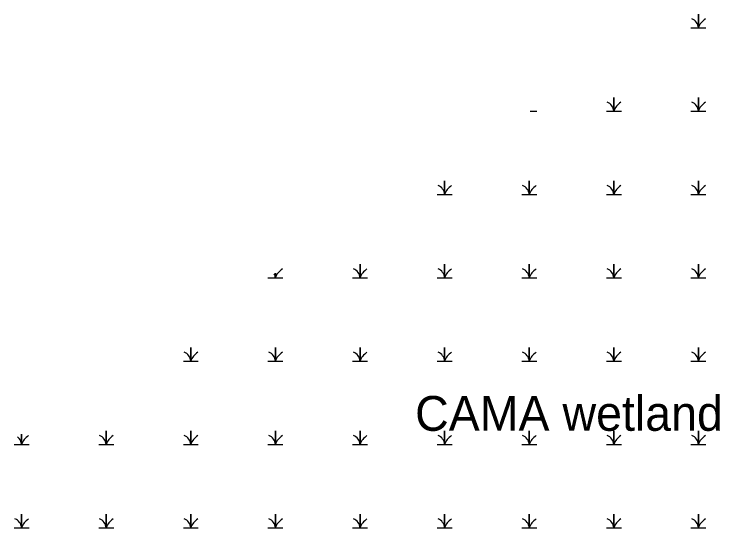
# Model space of a CAD drawing. Extents: x 2678633 to 2679425, y 623836 to 624637.
# Drawn here: x 2678767.1 to 2678969.9, y 624412.8 to 624560.4 of the extents above; entities that cross this region are included whole.
import ezdxf

# ---------------------------------------------------------------- set-up
doc = ezdxf.new("R2010")
doc.units = 0
doc.layers.add('Exist Environmental Wetland Boundary Text', color=7, linetype='Continuous')
doc.layers.add('Exist Hydro Swamp or Marsh', color=7, linetype='Continuous')

msp = doc.modelspace()

# ---------------------------------------------------------------- linework, layer by layer
at = {"layer": 'Exist Hydro Swamp or Marsh'}
for points in [[(2678961.59, 624556.5), (2678963.74, 624556.5), (2678963.74, 624560.45), (2678963.74, 624556.5), (2678965.89, 624556.5)], [(2678937.28, 624532.55), (2678939.43, 624532.55), (2678939.43, 624536.5), (2678939.43, 624532.55), (2678941.58, 624532.55)], [(2678961.59, 624532.55), (2678963.74, 624532.55), (2678963.74, 624536.5), (2678963.74, 624532.55), (2678965.89, 624532.55)], [(2678915.39, 624532.55), (2678917.27, 624532.55)], [(2678888.65, 624508.6), (2678890.8, 624508.6), (2678890.8, 624512.55), (2678890.8, 624508.6), (2678892.95, 624508.6)], [(2678912.97, 624508.6), (2678915.12, 624508.6), (2678915.12, 624512.55), (2678915.12, 624508.6), (2678917.27, 624508.6)], [(2678937.28, 624508.6), (2678939.43, 624508.6), (2678939.43, 624512.55), (2678939.43, 624508.6), (2678941.58, 624508.6)], [(2678961.59, 624508.6), (2678963.74, 624508.6), (2678963.74, 624512.55), (2678963.74, 624508.6), (2678965.89, 624508.6)], [(2678864.34, 624484.65), (2678866.49, 624484.65), (2678866.49, 624488.6), (2678866.49, 624484.65), (2678868.64, 624484.65)], [(2678888.65, 624484.65), (2678890.8, 624484.65), (2678890.8, 624488.6), (2678890.8, 624484.65), (2678892.95, 624484.65)], [(2678912.97, 624484.65), (2678915.12, 624484.65), (2678915.12, 624488.6), (2678915.12, 624484.65), (2678917.27, 624484.65)], [(2678937.28, 624484.65), (2678939.43, 624484.65), (2678939.43, 624488.6), (2678939.43, 624484.65), (2678941.58, 624484.65)], [(2678961.59, 624484.65), (2678963.74, 624484.65), (2678963.74, 624488.6), (2678963.74, 624484.65), (2678965.89, 624484.65)], [(2678840.03, 624484.65), (2678842.18, 624484.65), (2678842.18, 624486.04)], [(2678842.18, 624486.04), (2678842.18, 624484.65), (2678844.33, 624484.65)], [(2678815.72, 624460.7), (2678817.87, 624460.7), (2678817.87, 624464.65), (2678817.87, 624460.7), (2678820.02, 624460.7)], [(2678840.03, 624460.7), (2678842.18, 624460.7), (2678842.18, 624464.65), (2678842.18, 624460.7), (2678844.33, 624460.7)], [(2678864.34, 624460.7), (2678866.49, 624460.7), (2678866.49, 624464.65), (2678866.49, 624460.7), (2678868.64, 624460.7)], [(2678888.65, 624460.7), (2678890.8, 624460.7), (2678890.8, 624464.65), (2678890.8, 624460.7), (2678892.95, 624460.7)], [(2678912.97, 624460.7), (2678915.12, 624460.7), (2678915.12, 624464.65), (2678915.12, 624460.7), (2678917.27, 624460.7)], [(2678937.28, 624460.7), (2678939.43, 624460.7), (2678939.43, 624464.65), (2678939.43, 624460.7), (2678941.58, 624460.7)], [(2678961.59, 624460.7), (2678963.74, 624460.7), (2678963.74, 624464.65), (2678963.74, 624460.7), (2678965.89, 624460.7)], [(2678791.4, 624436.75), (2678793.55, 624436.75), (2678793.55, 624440.7), (2678793.55, 624436.75), (2678795.7, 624436.75)], [(2678815.72, 624436.75), (2678817.87, 624436.75), (2678817.87, 624440.7), (2678817.87, 624436.75), (2678820.02, 624436.75)], [(2678840.03, 624436.75), (2678842.18, 624436.75), (2678842.18, 624440.7), (2678842.18, 624436.75), (2678844.33, 624436.75)], [(2678864.34, 624436.75), (2678866.49, 624436.75), (2678866.49, 624440.7), (2678866.49, 624436.75), (2678868.64, 624436.75)], [(2678888.65, 624436.75), (2678890.8, 624436.75), (2678890.8, 624440.7), (2678890.8, 624436.75), (2678892.95, 624436.75)], [(2678912.97, 624436.75), (2678915.12, 624436.75), (2678915.12, 624440.7), (2678915.12, 624436.75), (2678917.27, 624436.75)], [(2678937.28, 624436.75), (2678939.43, 624436.75), (2678939.43, 624440.7), (2678939.43, 624436.75), (2678941.58, 624436.75)], [(2678961.59, 624436.75), (2678963.74, 624436.75), (2678963.74, 624440.7), (2678963.74, 624436.75), (2678965.89, 624436.75)], [(2678767.09, 624436.75), (2678769.24, 624436.75), (2678769.24, 624439.7)], [(2678769.24, 624439.7), (2678769.24, 624436.75), (2678771.39, 624436.75)], [(2678767.09, 624412.8), (2678769.24, 624412.8), (2678769.24, 624416.75), (2678769.24, 624412.8), (2678771.39, 624412.8)], [(2678791.4, 624412.8), (2678793.55, 624412.8), (2678793.55, 624416.75), (2678793.55, 624412.8), (2678795.7, 624412.8)], [(2678815.72, 624412.8), (2678817.87, 624412.8), (2678817.87, 624416.75), (2678817.87, 624412.8), (2678820.02, 624412.8)], [(2678840.03, 624412.8), (2678842.18, 624412.8), (2678842.18, 624416.75), (2678842.18, 624412.8), (2678844.33, 624412.8)], [(2678864.34, 624412.8), (2678866.49, 624412.8), (2678866.49, 624416.75), (2678866.49, 624412.8), (2678868.64, 624412.8)], [(2678888.65, 624412.8), (2678890.8, 624412.8), (2678890.8, 624416.75), (2678890.8, 624412.8), (2678892.95, 624412.8)], [(2678912.97, 624412.8), (2678915.12, 624412.8), (2678915.12, 624416.75), (2678915.12, 624412.8), (2678917.27, 624412.8)], [(2678937.28, 624412.8), (2678939.43, 624412.8), (2678939.43, 624416.75), (2678939.43, 624412.8), (2678941.58, 624412.8)], [(2678961.59, 624412.8), (2678963.74, 624412.8), (2678963.74, 624416.75), (2678963.74, 624412.8), (2678965.89, 624412.8)]]:
    msp.add_lwpolyline(points, dxfattribs=at)
for centre, radius, start, end in [((2678960.67, 624556.28), 3.07, 4.1403, 67.535), ((2678968.3, 624554.99), 4.81, 122.1274, 161.6222), ((2678936.36, 624532.33), 3.07, 4.1403, 67.535), ((2678943.99, 624531.04), 4.81, 122.1274, 161.6222), ((2678960.67, 624532.33), 3.07, 4.1403, 67.535), ((2678968.3, 624531.04), 4.81, 122.1274, 161.6222), ((2678887.74, 624508.38), 3.07, 4.1403, 67.535), ((2678895.36, 624507.09), 4.81, 122.1274, 161.6222), ((2678912.05, 624508.38), 3.07, 4.1403, 67.535), ((2678919.68, 624507.09), 4.81, 122.1274, 161.6222), ((2678936.36, 624508.38), 3.07, 4.1403, 67.535), ((2678943.99, 624507.09), 4.81, 122.1274, 161.6222), ((2678960.67, 624508.38), 3.07, 4.1403, 67.535), ((2678968.3, 624507.09), 4.81, 122.1274, 161.6222), ((2678846.74, 624483.14), 4.81, 122.1274, 161.6222), ((2678863.42, 624484.43), 3.07, 4.1403, 67.535), ((2678871.05, 624483.14), 4.81, 122.1274, 161.6222), ((2678887.74, 624484.43), 3.07, 4.1403, 67.535), ((2678895.36, 624483.14), 4.81, 122.1274, 161.6222), ((2678912.05, 624484.43), 3.07, 4.1403, 67.535), ((2678919.68, 624483.14), 4.81, 122.1274, 161.6222), ((2678936.36, 624484.43), 3.07, 4.1403, 67.535), ((2678943.99, 624483.14), 4.81, 122.1274, 161.6222), ((2678960.67, 624484.43), 3.07, 4.1403, 67.535), ((2678968.3, 624483.14), 4.81, 122.1274, 161.6222), ((2678839.11, 624484.43), 3.07, 4.1403, 27.0757), ((2678814.8, 624460.48), 3.07, 4.1403, 67.535), ((2678822.43, 624459.19), 4.81, 122.1274, 161.6222), ((2678839.11, 624460.48), 3.07, 4.1403, 67.535), ((2678846.74, 624459.19), 4.81, 122.1274, 161.6222), ((2678863.42, 624460.48), 3.07, 4.1403, 67.535), ((2678871.05, 624459.19), 4.81, 122.1274, 161.6222), ((2678887.74, 624460.48), 3.07, 4.1403, 67.535), ((2678895.36, 624459.19), 4.81, 122.1274, 161.6222), ((2678912.05, 624460.48), 3.07, 4.1403, 67.535), ((2678919.68, 624459.19), 4.81, 122.1274, 161.6222), ((2678936.36, 624460.48), 3.07, 4.1403, 67.535), ((2678943.99, 624459.19), 4.81, 122.1274, 161.6222), ((2678960.67, 624460.48), 3.07, 4.1403, 67.535), ((2678968.3, 624459.19), 4.81, 122.1274, 161.6222), ((2678766.17, 624436.53), 3.07, 4.1403, 51.9567), ((2678773.8, 624435.24), 4.81, 122.1274, 161.6222), ((2678790.49, 624436.53), 3.07, 4.1403, 67.535), ((2678798.11, 624435.24), 4.81, 122.1274, 161.6222), ((2678814.8, 624436.53), 3.07, 4.1403, 67.535), ((2678822.43, 624435.24), 4.81, 122.1274, 161.6222), ((2678839.11, 624436.53), 3.07, 4.1403, 67.535), ((2678846.74, 624435.24), 4.81, 122.1274, 161.6222), ((2678863.42, 624436.53), 3.07, 4.1403, 67.535), ((2678871.05, 624435.24), 4.81, 122.1274, 161.6222), ((2678887.74, 624436.53), 3.07, 4.1403, 67.535), ((2678895.36, 624435.24), 4.81, 122.1274, 161.6222), ((2678912.05, 624436.53), 3.07, 4.1403, 67.535), ((2678919.68, 624435.24), 4.81, 122.1274, 161.6222), ((2678936.36, 624436.53), 3.07, 4.1403, 67.535), ((2678943.99, 624435.24), 4.81, 122.1274, 161.6222), ((2678960.67, 624436.53), 3.07, 4.1403, 67.535), ((2678968.3, 624435.24), 4.81, 122.1274, 161.6222), ((2678766.17, 624412.58), 3.07, 4.1403, 67.535), ((2678773.8, 624411.29), 4.81, 122.1274, 161.6222), ((2678790.49, 624412.58), 3.07, 4.1403, 67.535), ((2678798.11, 624411.29), 4.81, 122.1274, 161.6222), ((2678814.8, 624412.58), 3.07, 4.1403, 67.535), ((2678822.43, 624411.29), 4.81, 122.1274, 161.6222), ((2678839.11, 624412.58), 3.07, 4.1403, 67.535), ((2678846.74, 624411.29), 4.81, 122.1274, 161.6222), ((2678863.42, 624412.58), 3.07, 4.1403, 67.535), ((2678871.05, 624411.29), 4.81, 122.1274, 161.6222), ((2678887.74, 624412.58), 3.07, 4.1403, 67.535), ((2678895.36, 624411.29), 4.81, 122.1274, 161.6222), ((2678912.05, 624412.58), 3.07, 4.1403, 67.535), ((2678919.68, 624411.29), 4.81, 122.1274, 161.6222), ((2678936.36, 624412.58), 3.07, 4.1403, 67.535), ((2678943.99, 624411.29), 4.81, 122.1274, 161.6222), ((2678960.67, 624412.58), 3.07, 4.1403, 67.535), ((2678968.3, 624411.29), 4.81, 122.1274, 161.6222)]:
    msp.add_arc(centre, radius, start, end, dxfattribs=at)

# ---------------------------------------------------------------- texts
at = {"layer": 'Exist Environmental Wetland Boundary Text'}
msp.add_text('CAMA wetland', height=10, dxfattribs=at).set_placement((2678882.32, 624440.7))

doc.saveas('drawing.dxf')
